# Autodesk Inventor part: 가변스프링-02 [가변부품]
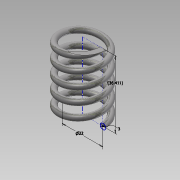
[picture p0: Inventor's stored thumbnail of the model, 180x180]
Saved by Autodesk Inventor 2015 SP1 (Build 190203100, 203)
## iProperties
Created: 2014-12
Part Number: 가변스프링-02 [가변부품]
Material: 강철, 탄소
Document SubType Name: Modeling
Designer: jhkwon
Density: 7.85 g/cm^3
Appearance: 반연마
Mass: 18.8392 g
Surface Area: 32.5593 cm^2
Volume: 2.39989 cm^3
Author: jhkwon
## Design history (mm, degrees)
sketch "스케치1"
  geometry: L1 (0, 0)-(-11, 0); L2 (-11, 0)-(-11, 36.411); L3 (-11, 36.411)-(0, 36.411); L4 (0, 36.411)-(0, 0); C1 r 1.5 at (-11, 0); 1 further point
  constraints: 8 end point, 2 coincident, 2 parallel, 1 centre point, 1 horizontal, 1 perpendicular
  dimensions: "d0" = 3 diameter of C1; "d1" = 22 diameter of L2 L4; "d4" = 36.4112 distance of L1.end L2.end (derived)
feature "코일1" sketch "스케치1" pitch "d5" = 10; turns "d7" = 5; dims "d6" = 36.4112 (= d4), "d8" = 0, angle "d9" = 90 deg, angle "d10" = 90 deg, "d11" = 0, "d12" = 0
sketch "스케치2"
  geometry: L1 (12.5, 0)-(9.5, 0) reference; 1 further point
  constraints: 1 horizontal alignment
extrude "돌출1" cut sketch "스케치2" distance "d13" = 10; taper "d14" = 0 deg
node "작업 평면1"
sketch "스케치3"
  geometry: L1 (0, 0)-(3, 0) reference; 1 further point
  constraints: 1 horizontal alignment
extrude "돌출2" cut sketch "스케치3" distance "d15" = 10; taper "d16" = 0 deg
node "솔리드1"
node "절단 모서리 투영1"
node "절단 모서리 투영2"
